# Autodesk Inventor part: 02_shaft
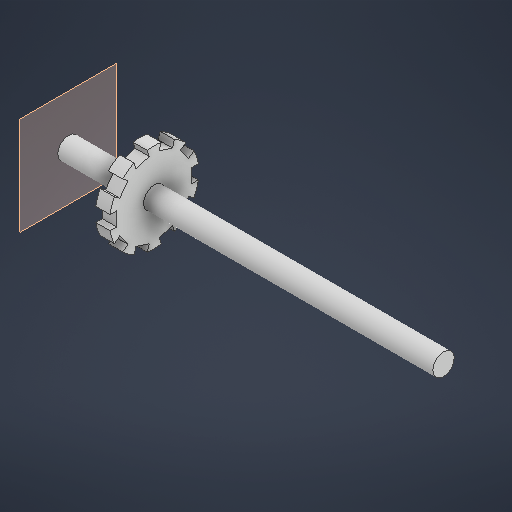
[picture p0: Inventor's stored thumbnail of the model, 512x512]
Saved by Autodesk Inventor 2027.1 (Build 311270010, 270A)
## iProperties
Created: 2026-10
Part Number: 02_shaft
Material: Generic
Document SubType Name: Modeling
Designer: BHAVAN KUMAR
Density: 1 g/cm^3
Appearance: Default
Author: BHAVAN KUMAR
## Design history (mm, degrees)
sketch "Sketch1"
  geometry: L1 (0, 0)-(407.76, 0); L2 (0, 6)-(210, 6); L3 (210, 6)-(210, 0); L4 (210, 0)-(0, 0); L5 (0, 0)-(0, 6); 2 further points
  constraints: 10 end point, 2 horizontal, 2 parallel, 1 perpendicular, 1 point on line
  dimensions: "d1" = 210 distance of L2.start L2.end (= shaft_len); "d2" = 12 diameter of L2 L1 (= shaft_dia); "d3" = 0 distance from line of L1.start L5
revolve "Shaft_Body" sketch "Sketch1" stored, may be unused: angle "d4" = 90 deg
workplane "Work Plane1"
sketch "Sketch2"
  geometry: L1 (3.9, 21)-(-3.9, 21); L2 (-3.9, 21)-(-3.9, 24.694); L3 (3.9, 24.694)-(3.9, 21); C1 r 6 at (0, 0) reference; C2 r 6 at (0, 0) reference; C3 r 6 at (0, 0) reference; A1 r 25 centre (0, 0) between (3.9, 24.694) and (-3.9, 24.694); 3 further points
  constraints: 6 end point, 2 point on circle, 1 centre point, 1 coincident, 1 horizontal, 1 parallel, 1 perpendicular
  dimensions: "d6" = 50 diameter of A1 (= tone_od); "d9" = 7.8 distance of L1.start L1.end (= slot_w); "d11" = 21 distance from line of point (0, 0) L1 (= 0.5 x tone_od - slot_depth); "d13" = 3.9 distance from line of point (0, 0) L3
  node "Projected Loop1"
extrude "ToneWheel_Disc" join sketch "Sketch2" distance "d7" = 8 (= tone_t); taper "d8" = 0 deg
extrude "ToneWheel_Slot" cut sketch "Sketch2" distance "d14" = 8 (= tone_t); taper "d15" = 0 deg
pattern_circular "ToneWheel_Pattern" dims angle "d17" = 360 deg
body "Solid1"
other parameters: "shaft_len" = 210 [user parameter; used in 1 equation term], "shaft_dia" = 12 [user parameter; used in 1 equation term], "tone_od" = 50 [user parameter; used in 2 equation terms], "tone_t" = 8 [user parameter; used in 2 equation terms], "slot_depth" = 4 [user parameter; used in 1 equation term], "slot_w" = 7.8 [user parameter; used in 1 equation term]
